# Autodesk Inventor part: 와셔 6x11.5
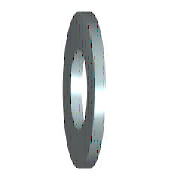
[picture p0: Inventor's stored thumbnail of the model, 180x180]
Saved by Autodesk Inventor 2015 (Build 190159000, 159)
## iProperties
IsCustomPart: 1
Created: 2012-02
Part Number: 와셔 6x11.5
Material: 강철, 연강
Description: 평면 와셔
Document SubType Name: Modeling
Standard: KS B 1326
Designer: mduedu
Standards Organization: KS
Language: ko-KR
Size Designation: 6x11.5
Categories: <MemberInstance><Categories><Category DisplayName="조임쇠" InternalName="e4da775c-781d-43d5-af7c-5136215cf5a6" Mnemonic="FSTN"><Category DisplayName="와셔" InternalN
Density: 1 g/cm^3
Appearance: 주황색
Author: mduedu
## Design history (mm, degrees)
sketch "스케치"
  geometry: C1 r 5.75 at (0, 0); C2 r 3.2 at (0, 0); 1 further point
  constraints: 2 centre point, 2 coincident
  dimensions: "d0" = 6.4 diameter of C2 (= SD1); "d1" = 11.5 diameter of C1 (= SD2)
extrude "본체" new body sketch "스케치" distance "d2" = 1.6 (= SD); taper "d3" = 0 deg
workaxis "Work Axis1"
workplane "Work Plane1"
body "Solid1"
other parameters: "SD1" = 6.4 [user parameter; used in 1 equation term], "SD2" = 11.5 [user parameter; used in 1 equation term], "SD" = 1.6 [user parameter; used in 1 equation term], "d4" = 0, "d5" = 0, "d6" = 0, "d7" = 0, "NND" = 6 [user parameter]
